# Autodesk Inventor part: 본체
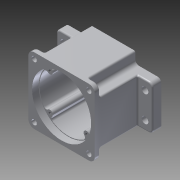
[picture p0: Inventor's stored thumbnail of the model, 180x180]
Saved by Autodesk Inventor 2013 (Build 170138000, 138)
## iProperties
Created: 2015-07
Part Number: 본체
Material: 알루미늄 6061
Document SubType Name: Modeling
Designer: user
Density: 1 g/cm^3
Author: user
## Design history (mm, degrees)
sketch "스케치1"
  geometry: L1 (-45, -45)-(45, -45); L2 (45, -45)-(45, 45); L3 (45, 45)-(-45, 45); L4 (-45, 45)-(-45, -45); 3 further points
  constraints: 8 end point, 2 midpoint, 2 parallel, 1 horizontal, 1 horizontal alignment, 1 perpendicular, 1 vertical alignment
  dimensions: "d0" = 90 distance of L3.end L2.end; "d1" = 90 distance of L2.end L1.end
extrude "돌출1" new body sketch "스케치1" distance "d2" = 70; taper "d3" = 0 deg
sketch "스케치2"
  geometry: L1 (-45, 45)-(-45, -45) reference; L2 (-45, 0)-(-45, 30); L3 (-45, 0)-(-45, -30); L4 (-45, -30)-(-65, -30); L5 (-65, -30)-(-65, 30); L6 (-65, 30)-(-45, 30); 1 further point
  constraints: 10 end point, 3 perpendicular, 2 point on line, 1 midpoint
  dimensions: "d4" = 30 distance of L2.start L2.end; "d5" = 30 distance of L2.start L3.end; "d6" = 20 distance of L3.end L4.end
extrude "돌출2" join sketch "스케치2" distance "d7" = 12; taper "d8" = 0 deg
node "작업 평면1"
sketch "스케치3"
  geometry: L1 (-45, 45)-(-45, 30) reference; L2 (65, 30)-(65, -30) reference; L3 (45, 30)-(65, 30) reference; L4 (45, 30)-(45, 45) reference; L5 (-30, 45)-(-30, 30); L6 (-30, 30)-(-45, 30); L7 (-45, 45)-(-30, 45); L8 (-45, 30)-(-45, 45); 1 further point
  constraints: 8 end point, 2 parallel, 1 collinear, 1 perpendicular
  dimensions: "d10" = 95 distance between parallel lines of L2 L5
extrude "돌출3" cut sketch "스케치3" distance "d11" = 63; taper "d12" = 0 deg
node "작업 평면2"
sketch "스케치4"
  geometry: C1 r 40 at (0, 0); 1 further point
  constraints: 1 centre point, 1 coincident
  dimensions: "d13" = 80 diameter of C1
extrude "돌출4" cut sketch "스케치4" distance "d14" = 9; taper "d15" = 0 deg
sketch "스케치5"
  geometry: C1 r 40 at (0, 0) reference; C2 r 39 at (0, 0)
  constraints: 1 centre point, 1 coincident
  dimensions: "d16" = 78 diameter of C2
extrude "돌출5" cut sketch "스케치5" distance "d17" = 52; taper "d18" = 0 deg
sketch "스케치6"
  geometry: L1 (0, 0)-(0, 11); L2 (0, 0)-(0, -20); C1 r 39 at (0, 0) reference; A1 r 20.5 centre (0, 11) between (11.115, -6.225) and (-11.115, -6.225); A2 r 14 centre (0, -20) between (-10.493, -10.732) and (10.493, -10.732); A3 r 3 centre (-12.742, -8.746) between (-10.493, -10.732) and (-11.115, -6.225); A4 r 3 centre (12.742, -8.746) between (11.115, -6.225) and (10.493, -10.732)
  constraints: 8 point on circle, 4 centre point, 4 end point, 4 tangent, 2 coincident, 1 collinear, 1 equal radius, 1 vertical
  dimensions: "d19" = 11 distance of L1.start L1.end; "d20" = 41 diameter of A1; "d21" = 20 distance of L1.start L2.end; "d22" = 28 diameter of A2; "d23" = 3 radius of A3
extrude "돌출6" join sketch "스케치6" distance "d24" = 7; taper "d25" = 0 deg
sketch "스케치7"
  geometry: C1 r 17.5 at (0, 11); A1 r 20.5 centre (0, 11) between (11.115, -6.225) and (-11.115, -6.225) reference; 1 further point
  constraints: 1 centre point, 1 coincident
  dimensions: "d26" = 35 diameter of C1
extrude "돌출7" cut sketch "스케치7" distance "d27" = 10; taper "d28" = 0 deg
sketch "스케치8"
  geometry: C1 r 17.5 at (0, 0) reference; C2 r 12.5 at (0, 0); 1 further point
  constraints: 1 centre point, 1 coincident
  dimensions: "d29" = 25 diameter of C2
extrude "돌출8" cut sketch "스케치8" distance "d30" = 5; taper "d31" = 0 deg
sketch "스케치9"
  geometry: C1 r 12.5 at (0, 0) reference; C2 r 16 at (0, 0); 1 further point
  constraints: 1 centre point, 1 coincident
  dimensions: "d32" = 32 diameter of C2
sketch "스케치11"
  geometry: L1 (65, 30)-(65, -30) reference; L2 (65, 30)-(30, 30) reference; C1 r 25 at (0, -11); 1 further point
  constraints: 1 centre point
  dimensions: "d35" = 50 diameter of C1; "d36" = 41 distance from line of C1.centre L2; "d37" = 65 distance from line of C1.centre L1
extrude "돌출9" join sketch "스케치11" distance "d38" = 7; taper "d39" = 0 deg
extrude "돌출10" cut sketch "스케치9" distance "d40" = 8; taper "d41" = 0 deg
sketch "스케치12"
  geometry: C1 r 11 at (0, -20); A1 r 14 centre (0, -20) between (-10.493, -10.732) and (10.493, -10.732) reference; 1 further point
  constraints: 1 centre point, 1 coincident
  dimensions: "d42" = 22 diameter of C1
extrude "돌출11" cut sketch "스케치12" distance "d43" = 7; taper "d44" = 0 deg
sketch "스케치13"
  geometry: C1 r 11 at (0, 0) reference; C2 r 9.5 at (0, 0); 1 further point
  constraints: 1 centre point, 1 coincident
  dimensions: "d45" = 19 diameter of C2
extrude "돌출12" cut sketch "스케치13" distance "d46" = 1; taper "d47" = 0 deg
fillet "모깎기1" dims "d48" = 3
sketch "스케치14"
  geometry: L1 (-38.997, -0.444)-(-42.637, -0.444); C1 r 40 at (0, 0) reference; A1 r 39 centre (0, 0) between (-39, 0) and (-38.997, -0.444); A2 r 3.5 centre (19.238, 29.836) between (21.809, 27.462) and (21.134, 32.777); A3 r 4 centre (24.749, 24.749) between (21.809, 27.462) and (27.462, 21.809); A4 r 3.5 centre (29.836, 19.238) between (32.777, 21.134) and (27.462, 21.809); A5 r 39 centre (0, 0) between (32.777, 21.134) and (21.134, 32.777)
  constraints: 10 point on circle, 6 tangent, 5 centre point, 2 end point, 1 coincident, 1 concentric, 1 horizontal
  dimensions: "d53" = 3.5 radius of A2; "d54" = 3.5 radius of A4; "d55" = 78 diameter of A5; "d56" = 4 radius of A3; "d57" = 0.44441 distance from line of C1.centre L1; "d58" = 21.57862 distance from line of A4.start L1; "d59" = 0.44441 distance from line of A1.start L1; "d60" = 42.6397 distance of L1.end C1.centre
extrude "돌출13" join sketch "스케치14" distance "d61" = 52; taper "d62" = 0 deg
sketch "스케치15"
  geometry: A1 r 4 centre (24.749, 24.749) between (21.809, 27.462) and (27.462, 21.809) reference; A2 r 4 centre (24.749, -24.749) between (27.462, -21.809) and (21.809, -27.462) reference; A3 r 4 centre (-24.749, -24.749) between (-21.809, -27.462) and (-27.462, -21.809) reference; A4 r 4 centre (-24.749, 24.749) between (-27.462, 21.809) and (-21.809, 27.462) reference
hole "구멍1" sketch "스케치15" at (24.749, 24.749), (-24.749, 24.749), (-24.749, -24.749), (24.749, -24.749) diameter "d66" = 3.459; stored, may be unused: countersink angle "d70" = 90 deg, drill point angle "d72" = 118 deg; dims "d67" = 12, "d68" = 4, "d69" = 2, "d71" = 15
fillet "모깎기2" dims "d73" = 5
sketch "스케치17"
  geometry: L1 (-45, 30)-(-45, -30) reference; L2 (-45, 30)-(-60, 30) reference; C1 r 4.5 at (-55, 17.5); 1 further point
  constraints: 1 centre point
  dimensions: "d76" = 9 diameter of C1; "d77" = 12.5 distance from line of C1.centre L2; "d78" = 10 distance from line of C1.centre L1
extrude "돌출14" cut sketch "스케치17" stored distance "d79" = 1; taper "d80" = 0 deg
sketch "스케치18"
  geometry: L1 (45, -45)-(-45, -45) reference; L2 (45, 45)-(45, -45) reference; C1 r 3.5 at (-37, 37)
  constraints: 1 centre point
  dimensions: "d83" = 7 diameter of C1; "d84" = 82 distance from line of C1.centre L2; "d85" = 82 distance from line of C1.centre L1
extrude "돌출15" cut sketch "스케치18" distance "d86" = 30; taper "d87" = 0 deg
chamfer "모따기1" distance "d88" = 1; stored, may be unused: second distance "d89" = 2, angle "d90" = 45 deg
chamfer "모따기2" distance "d91" = 1; stored, may be unused: second distance "d92" = 2, angle "d93" = 45 deg
fillet "모깎기3" dims "d94" = 0.3
fillet "모깎기4" dims "d95" = 0.3
fillet "모깎기5" dims "d96" = 0.3
fillet "모깎기6" dims "d97" = 2
fillet "모깎기7" dims "d98" = 8
fillet "모깎기8" dims "d99" = 5
fillet "모깎기9" dims "d100" = 2
fillet "모깎기10" dims "d101" = 2
fillet "모깎기11" dims "d102" = 5
fillet "모깎기12" dims "d103" = 2
fillet "모깎기13" dims "d104" = 2
fillet "모깎기14" dims "d105" = 2
fillet "모깎기15" dims "d106" = 2
sketch "스케치19"
  geometry: L1 (28, 45)-(-28, 45) reference; L2 (-30, -35)-(-30, -43) reference; L3 (0, 45)-(0, 30); 2 further points
  constraints: 2 end point, 1 coincident, 1 midpoint, 1 parallel, 1 other
  dimensions: "d107" = 15 distance of L3.start L3.end
feature "엠보싱1" sketch "스케치19" dims "d108" = 0.5, "d109" = 0
node "솔리드1"
mirror "대칭1"
mirror "대칭2"
mirror "대칭3"
pattern_circular "원형 패턴1" dims angle "d64" = 360 deg
mirror "대칭4"
mirror "대칭5"
mirror "대칭6"
mirror "대칭7"
